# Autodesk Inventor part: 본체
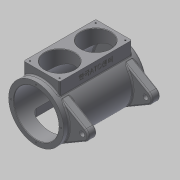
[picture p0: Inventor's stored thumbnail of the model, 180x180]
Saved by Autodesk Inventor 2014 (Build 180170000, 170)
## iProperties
Created: 2016-11
Part Number: 본체
Material: 일반
Document SubType Name: Modeling
Designer: mduedu
Density: 1 g/cm^3
Appearance: 기본값
Author: mduedu
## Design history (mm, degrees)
sketch "스케치1"
  geometry: C1 r 65 at (0, 0); 1 further point
  constraints: 1 centre point, 1 coincident
  dimensions: "d119" = 130 diameter of C1
extrude "돌출1" new body sketch "스케치1" distance "d3" = 98; taper "d4" = 0 deg; dims "d132" = 97, "d133" = 0
feature "쉘1" dims "d120" = 12, "d134" = 8
node "작업 평면2"
sketch "스케치13"
  geometry: L1 (42.5, 85)-(-42.5, 85); L2 (-42.5, 85)-(-42.5, -85); L3 (-42.5, -85)-(42.5, -85); L4 (42.5, -85)-(42.5, 85); 2 further points
  constraints: 8 end point, 2 parallel, 1 horizontal, 1 midpoint, 1 perpendicular, 1 vertical alignment
  dimensions: "d122" = 170 distance of L1.end L2.end; "d124" = 85 distance of L2.end L3.end; "d125" = 85 distance from line of point (0, 0) L1 (= 0.5 x d122)
extrude "돌출11" join sketch "스케치13" stored distance "d126" = 10; taper "d127" = 0 deg
sketch "스케치14"
  geometry: L1 (65, 97)-(-65, 97) reference; C1 r 35 at (0, 42.5); 1 further point
  constraints: 1 centre point, 1 vertical alignment
  dimensions: "d128" = 70 diameter of C1; "d129" = 54.5 distance from line of C1.centre L1
extrude "돌출12" cut sketch "스케치14" stored distance "d130" = 10; taper "d131" = 0 deg
sketch "스케치15"
  geometry: C1 r 53 at (0, 0) reference; 1 further point
extrude "돌출13" cut sketch "스케치15" stored distance "d135" = 10; taper "d136" = 0 deg
chamfer "모따기1" distance "d54" = 1; stored, may be unused: second distance "d55" = 2, angle "d56" = 45 deg
sketch "스케치8"
  geometry: C1 r 23 at (0, 0); C2 r 65 at (0, 0) reference; 1 further point
  constraints: 1 centre point, 1 concentric
  dimensions: "d57" = 46 diameter of C1
extrude "돌출8" join sketch "스케치8" distance "d58" = 14; taper "d59" = 0 deg
feature "면 기울기1" dims angle "d202" = 10 deg
hole "구멍3" diameter "d62" = 24; stored, may be unused: countersink angle "d66" = 90 deg, drill point angle "d68" = 0 deg; dims "d63" = 6, "d64" = 28, "d65" = 8, "d67" = 14, "d169" = 10, "d170" = 10
fillet "모깎기11" dims "d69" = 3
fillet "모깎기12" dims "d70" = 3
fillet "모깎기13" dims "d71" = 0.3
chamfer "모따기2" distance "d72" = 1; stored, may be unused: second distance "d73" = 2, angle "d74" = 45 deg
node "작업 평면3"
sketch "스케치16"
  geometry: L1 (-42.5, -80)-(52.5, -80); L2 (-42.5, -80)-(24.675, -12.825); L3 (-42.5, -80)-(24.675, -147.175); L4 (3.462, -34.038)-(60.057, -67.042); L5 (3.462, -125.962)-(60.057, -92.958); A1 r 65 centre (-42.5, -80) between (3.462, -34.038) and (3.462, -125.962) reference; A2 r 65 centre (-42.5, -80) between (3.462, -125.962) and (3.462, -34.038); A3 r 95 centre (-42.5, -80) between (52.5, -80) and (24.675, -147.175); A4 r 15 centre (52.5, -80) between (60.057, -67.042) and (60.057, -92.958); 1 further point
  constraints: 10 end point, 9 point on circle, 3 centre point, 3 coincident, 2 point on line, 2 tangent, 1 horizontal
  dimensions: "d140" = 45 deg angle of L3 L1; "d141" = 45 deg angle of L2 L1; "d194" = 30 radial gap between concentric circles of A3 A1; "d195" = 30 diameter of A4
extrude "돌출14" join sketch "스케치16" distance "d143" = 20; taper "d144" = 0 deg
fillet "모깎기25" dims "d196" = 3
fillet "모깎기26" dims "d197" = 3
sketch "스케치22"
  geometry: C1 r 6 at (52.5, -80); A1 r 15 centre (52.5, -80) between (60.057, -92.958) and (60.057, -67.042) reference; 1 further point
  constraints: 1 centre point, 1 coincident
  dimensions: "d198" = 12 diameter of C1
extrude "돌출17" cut sketch "스케치22" stored distance "d200" = 10; taper "d201" = 0 deg
fillet "모깎기20" dims "d159" = 3
fillet "모깎기21" dims "d160" = 3
fillet "모깎기22" dims "d161" = 3
node "작업 평면4"
sketch "스케치18"
  geometry: L1 (-42.5, 65)-(42.5, 65); L2 (42.5, 65)-(42.5, -65); L3 (42.5, -65)-(-42.5, -65); L4 (-42.5, -65)-(-42.5, 65); 2 further points
  constraints: 8 end point, 2 parallel, 1 horizontal, 1 midpoint, 1 perpendicular, 1 vertical alignment
  dimensions: "d162" = 130 distance of L1.end L2.end; "d164" = 85 distance of L2.end L3.end; "d165" = 65 distance from line of point (0, 0) L1 (= 0.5 x d162)
extrude "돌출16" cut sketch "스케치18" stored distance "d166" = 15; taper "d167" = 0 deg
fillet "모깎기23" dims "d168" = 10
fillet "모깎기24" dims "d173" = 3
sketch "스케치19"
  geometry: 4 further points
  constraints: 4 other
hole "구멍6" sketch "스케치19" at (0, -59), (59, 0), (-59, 0), (0, 59) diameter "d174" = 3.242; stored, may be unused: countersink angle "d178" = 90 deg, drill point angle "d180" = 120 deg; dims "d175" = 7, "d176" = 4, "d177" = 2, "d179" = 9
sketch "스케치20"
  geometry: L1 (35, -77.5)-(-35, -77.5); L2 (-35, -77.5)-(-35, -7.5); L3 (-35, -7.5)-(35, -7.5); L4 (35, -7.5)-(35, -77.5); L5 (35, -77.5)-(-35, -7.5); L6 (-35, -77.5)-(35, -7.5); C1 r 36 at (0, -42.5) reference; 3 further points
  constraints: 12 end point, 2 coincident, 2 midpoint, 2 parallel, 1 horizontal, 1 perpendicular
  dimensions: "d181" = 70 distance of L2.end L3.end; "d182" = 70 distance of L1.end L2.end
hole "구멍7" sketch "스케치20" at (-35, -77.5), (35, -77.5) diameter "d183" = 3.242; stored, may be unused: countersink angle "d187" = 90 deg, drill point angle "d189" = 118 deg; dims "d184" = 7, "d185" = 4, "d186" = 2, "d188" = 9
sketch "스케치21"
  geometry: L1 (164, 0)-(0, 0) reference; L2 (-3, 0)-(-3, -24.649) reference; 3 further points
  constraints: 1 midpoint, 1 vertical alignment, 1 other
  dimensions: "d190" = 15 distance from line of point (82, -15) L1; "d191" = 85 distance from line of point (82, 0) L2 (derived)
feature "엠보싱2" sketch "스케치21" dims "d119" = 130, "d192" = 0.5, "d193" = 0
node "솔리드1"
mirror "대칭5"
mirror "대칭6"
mirror "대칭7"
